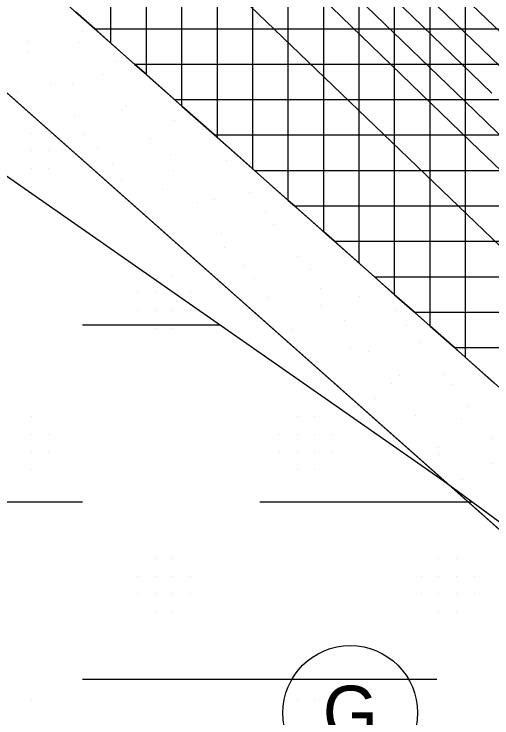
# Model space of a CAD drawing. Extents: x 409341 to 428634, y 4447481 to 4463281.
# Drawn here: x 419413.2 to 419547.9, y 4459096 to 4459294.6 of the extents above; entities that cross this region are included whole.
import ezdxf

# ---------------------------------------------------------------- set-up
doc = ezdxf.new("R2010")
doc.units = 0
for name, color, linetype in [('ADA', 7, 'Continuous'), ('Default', 7, 'Continuous'), ('LJ_SEMBOL', 7, 'Continuous'), ('PL_AYA_PARK_DINLENME', 7, 'Continuous'), ('PL_T_GUNUBIRLIK', 7, 'Continuous'), ('PL_TA_K_TERMINAL', 7, 'Continuous'), ('RAYLI_TOPLU_TAŞIMA_HATTI', 7, 'Continuous'), ('SN_TASKIN', 7, 'Continuous'), ('SN_TR_TASKIN', 7, 'Continuous'), ('TR_OTOTERMINAL', 7, 'Continuous'), ('TR_PARKALANI', 7, 'Continuous'), ('TR_TURIZM', 7, 'Continuous')]:
    doc.layers.add(name, color=color, linetype=linetype)

# ---------------------------------------------------------------- blocks, each defined once
blk = doc.blocks.new('POINT_DISPLAY')
at = {"layer": 'Default'}
blk.add_line((0, 0), (0, 0), dxfattribs=at)

msp = doc.modelspace()

# ---------------------------------------------------------------- linework, layer by layer
at = {"layer": 'ADA'}
for p, q in [((419593.69, 4459150.44), (419389.04, 4459332)), ((419575.67, 4459126.32), (419363.83, 4459314.26))]:
    msp.add_line(p, q, dxfattribs=at)
at = {"layer": 'LJ_SEMBOL'}
msp.add_circle((419507.98, 4459097.36), 19, dxfattribs=at)
at = {"layer": 'PL_AYA_PARK_DINLENME'}
for points in [[(419187.75, 4459624.15), (419274.22, 4459624.93), (419298.64, 4459476.64), (419363.83, 4459314.26), (419575.67, 4459126.32), (419851.88, 4458954.08)], [(419548.6, 4459190.44), (419540.49, 4459197.63), (419537.33, 4459200.44), (419530.49, 4459206.5), (419526.06, 4459210.44), (419520.49, 4459215.38), (419514.79, 4459220.44), (419510.49, 4459224.25), (419503.52, 4459230.44), (419500.49, 4459233.12), (419492.25, 4459240.44), (419490.49, 4459241.99), (419480.97, 4459250.44), (419480.49, 4459250.86), (419470.49, 4459259.73), (419469.7, 4459260.44), (419460.49, 4459268.61), (419458.43, 4459270.44), (419450.49, 4459277.48), (419447.16, 4459280.44), (419440.49, 4459286.35), (419435.89, 4459290.44), (419430.49, 4459295.22)]]:
    msp.add_lwpolyline(points, dxfattribs=at)
at = {"layer": 'PL_T_GUNUBIRLIK'}
msp.add_lwpolyline([(419851.88, 4458954.08), (419575.67, 4459126.32), (419363.83, 4459314.26), (419298.64, 4459476.64), (419274.22, 4459624.93), (419187.75, 4459624.15)], dxfattribs=at)
at = {"layer": 'PL_TA_K_TERMINAL'}
msp.add_lwpolyline([(419430.49, 4459295.22), (419435.89, 4459290.44), (419440.49, 4459286.35), (419447.16, 4459280.44), (419450.49, 4459277.48), (419458.43, 4459270.44), (419460.49, 4459268.61), (419469.7, 4459260.44), (419470.49, 4459259.73), (419480.49, 4459250.86), (419480.97, 4459250.44), (419490.49, 4459241.99), (419492.25, 4459240.44), (419500.49, 4459233.12), (419503.52, 4459230.44), (419510.49, 4459224.25), (419514.79, 4459220.44), (419520.49, 4459215.38), (419526.06, 4459210.44), (419530.49, 4459206.5), (419537.33, 4459200.44), (419540.49, 4459197.63), (419548.6, 4459190.44)], dxfattribs=at)
at = {"layer": 'RAYLI_TOPLU_TAŞIMA_HATTI'}
for p, q in [((419547.92, 4459272.27), (419456.62, 4459360.51)), ((419542.02, 4459258.51), (419448.72, 4459348.69)), ((419557.67, 4459282.32), (419500.9, 4459337.2)), ((419552.79, 4459277.31), (419496.03, 4459332.16)), ((419543.07, 4459267.23), (419481.44, 4459326.8)), ((419451.3, 4459324.16), (419585.7, 4459194.99)), ((419577.82, 4459233.64), (419543.07, 4459267.23)), ((419599.39, 4459203.05), (419542.02, 4459258.51))]:
    msp.add_line(p, q, dxfattribs=at)
at = {"layer": 'SN_TASKIN'}
msp.add_lwpolyline([(419185.75, 4459437.23), (419214.18, 4459402.24), (419272.57, 4459332.21), (419310.51, 4459304.19), (419405.96, 4459252.35), (419534.17, 4459162.95), (419773.68, 4458987.15), (419985.79, 4458863.31), (420128.07, 4458758.85)], dxfattribs=at)
at = {"layer": 'SN_TR_TASKIN'}
for p, q in [((419432.43, 4459206.9), (419471.14, 4459206.9)), ((419332.43, 4459156.9), (419432.43, 4459156.9)), ((419482.43, 4459156.9), (419542.41, 4459156.9)), ((419432.43, 4459106.9), (419532.43, 4459106.9))]:
    msp.add_line(p, q, dxfattribs=at)
at = {"layer": 'TR_OTOTERMINAL'}
for p, q in [((419440.49, 4459286.35), (419440.49, 4460032.77)), ((419450.49, 4459277.48), (419450.49, 4460005.82)), ((419460.49, 4459268.61), (419460.49, 4459978.87)), ((419470.49, 4459259.73), (419470.49, 4459951.92)), ((419480.49, 4459250.86), (419480.49, 4459924.98)), ((419490.49, 4459241.99), (419490.49, 4459898.03)), ((419500.49, 4459233.12), (419500.49, 4459871.08)), ((419510.49, 4459224.25), (419510.49, 4459844.13)), ((419520.49, 4459215.38), (419520.49, 4459631.89)), ((419530.49, 4459206.5), (419530.49, 4459605.66)), ((419540.49, 4459197.63), (419540.49, 4459591.67)), ((419435.89, 4459290.44), (419700.01, 4459290.44)), ((419447.16, 4459280.44), (419692.42, 4459280.44)), ((419458.43, 4459270.44), (419684.82, 4459270.44)), ((419469.7, 4459260.44), (419677.23, 4459260.44)), ((419480.97, 4459250.44), (419669.63, 4459250.44)), ((419492.25, 4459240.44), (419662.04, 4459240.44)), ((419503.52, 4459230.44), (419654.44, 4459230.44)), ((419514.79, 4459220.44), (419646.85, 4459220.44)), ((419526.06, 4459210.44), (419639.26, 4459210.44)), ((419537.33, 4459200.44), (419631.66, 4459200.44))]:
    msp.add_line(p, q, dxfattribs=at)

# ---------------------------------------------------------------- block references
at = {"layer": 'TR_PARKALANI', "xscale": 0.1, "yscale": 0.10000000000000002}
for p in [(419432.33, 4459289.55), (419417.35, 4459286.87), (419431.61, 4459286.43), (419431.61, 4459286.43), (419416.84, 4459283.83), (419416.84, 4459283.83), (419441.7, 4459281.19), (419441.7, 4459281.19), (419438.27, 4459277.45), (419438.27, 4459277.45), (419423.5, 4459274.85), (419423.5, 4459274.85), (419429.72, 4459274.78), (419414.08, 4459272.46), (419444.93, 4459268.47), (419444.93, 4459268.47), (419430.16, 4459265.87), (419430.16, 4459265.87), (419443.63, 4459267.25), (419458.4, 4459264.64), (419466.37, 4459262.1), (419466.37, 4459262.1), (419432.8, 4459260.67), (419451.59, 4459259.49), (419451.59, 4459259.49), (419436.82, 4459256.89), (419436.82, 4459256.89), (419457.15, 4459254.99), (419457.15, 4459254.99), (419441.02, 4459252.47), (419473.03, 4459253.12), (419473.03, 4459253.12), (419458.25, 4459250.51), (419458.25, 4459250.51), (419443.48, 4459247.91), (419443.48, 4459247.91), (419454.93, 4459244.95), (419479.69, 4459244.14), (419479.69, 4459244.14), (419485.34, 4459244.66), (419469.7, 4459242.34), (419464.91, 4459241.53), (419464.91, 4459241.53), (419450.14, 4459238.93), (419450.14, 4459238.93), (419484.1, 4459238.44), (419486.35, 4459235.16), (419486.35, 4459235.16), (419471.58, 4459232.55), (419471.58, 4459232.55), (419472.6, 4459228.8), (419472.6, 4459228.8), (419493.01, 4459226.18), (419493.01, 4459226.18), (419478.24, 4459223.57), (419478.24, 4459223.57), (419496.64, 4459222.36), (419481, 4459220.04), (419514.44, 4459219.8), (419514.44, 4459219.8), (419499.67, 4459217.2), (419499.67, 4459217.2), (419484.9, 4459214.59), (419484.9, 4459214.59), (419510.54, 4459214.83), (419499.55, 4459212.25), (419521.1, 4459210.82), (419521.1, 4459210.82), (419506.33, 4459208.22), (419506.33, 4459208.22), (419523.89, 4459206.57), (419523.89, 4459206.57), (419491.56, 4459205.61), (419491.56, 4459205.61), (419527.76, 4459201.84), (419527.76, 4459201.84), (419507.94, 4459200.06), (419512.99, 4459199.24), (419512.99, 4459199.24), (419498.22, 4459196.63), (419498.22, 4459196.63), (419521.84, 4459192.53), (419534.42, 4459192.86), (419534.42, 4459192.86), (419519.65, 4459190.26), (419519.65, 4459190.26), (419536.61, 4459189.93), (419515, 4459186.05), (419541.08, 4459183.88), (419541.08, 4459183.88), (419526.31, 4459181.28), (419526.31, 4459181.28), (419539.35, 4459180.37), (419539.35, 4459180.37), (419519.24, 4459177.76), (419547.74, 4459174.9), (419547.74, 4459174.9), (419532.97, 4459172.3), (419532.97, 4459172.3), (419533.14, 4459170.23), (419547.91, 4459167.62), (419539.63, 4459163.32), (419539.63, 4459163.32), (419546.29, 4459154.34), (419546.29, 4459154.34)]:
    msp.add_blockref('POINT_DISPLAY', p, dxfattribs=at)
at = {"layer": 'TR_TURIZM', "xscale": 0.1, "yscale": 0.10000000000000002}
for p in [(419417.98, 4459260.93), (419417.98, 4459255.93), (419422.98, 4459255.93), (419417.98, 4459250.93), (419422.98, 4459250.93), (419417.98, 4459245.93), (419452.98, 4459220.93), (419457.98, 4459220.93), (419447.98, 4459215.93), (419452.98, 4459215.93), (419457.98, 4459215.93), (419462.98, 4459215.93), (419447.98, 4459210.93), (419452.98, 4459210.93), (419457.98, 4459210.93), (419462.98, 4459210.93), (419452.98, 4459205.93), (419457.98, 4459205.93), (419417.98, 4459180.93), (419492.98, 4459180.93), (419497.98, 4459180.93), (419417.98, 4459175.93), (419422.98, 4459175.93), (419487.98, 4459175.93), (419492.98, 4459175.93), (419497.98, 4459175.93), (419502.98, 4459175.93), (419417.98, 4459170.93), (419422.98, 4459170.93), (419487.98, 4459170.93), (419492.98, 4459170.93), (419497.98, 4459170.93), (419502.98, 4459170.93), (419417.98, 4459165.93), (419492.98, 4459165.93), (419497.98, 4459165.93), (419452.98, 4459140.93), (419457.98, 4459140.93), (419532.98, 4459140.93), (419537.98, 4459140.93), (419447.98, 4459135.93), (419452.98, 4459135.93), (419457.98, 4459135.93), (419462.98, 4459135.93), (419527.98, 4459135.93), (419532.98, 4459135.93), (419537.98, 4459135.93), (419542.98, 4459135.93), (419447.98, 4459130.93), (419452.98, 4459130.93), (419457.98, 4459130.93), (419462.98, 4459130.93), (419527.98, 4459130.93), (419532.98, 4459130.93), (419537.98, 4459130.93), (419542.98, 4459130.93), (419452.98, 4459125.93), (419457.98, 4459125.93), (419532.98, 4459125.93), (419537.98, 4459125.93), (419417.98, 4459100.93), (419492.98, 4459100.93), (419497.98, 4459100.93)]:
    msp.add_blockref('POINT_DISPLAY', p, dxfattribs=at)

# ---------------------------------------------------------------- texts
at = {"layer": 'LJ_SEMBOL'}
msp.add_text('G', height=15, dxfattribs=at).set_placement((419500.23, 4459090.03))

doc.saveas('drawing.dxf')
